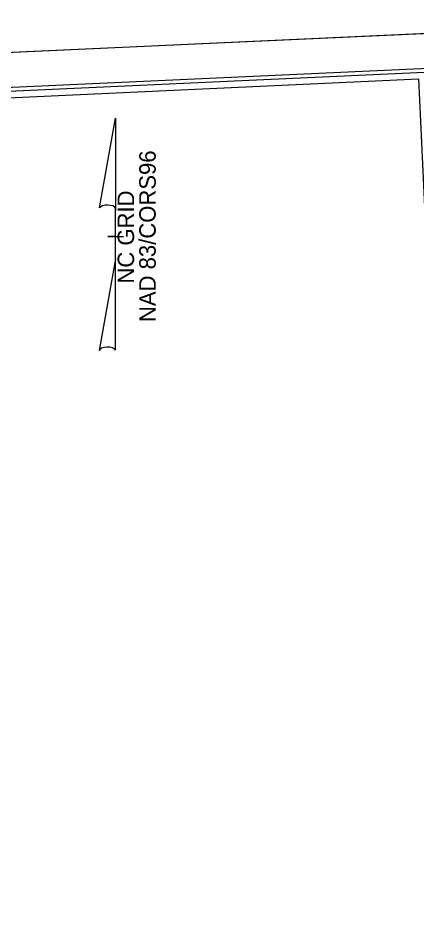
# Model space of a CAD drawing. Extents: x 1191067 to 1191874, y 892813 to 893283.
# Drawn here: x 1191598.1 to 1191700.8, y 893048.3 to 893283.5 of the extents above; entities that cross this region are included whole.
import ezdxf

# ---------------------------------------------------------------- set-up
doc = ezdxf.new("R2010")
doc.units = 0
for name, color, linetype in [('Prop North Arrow NAD83 for Plan Sheets CELL', 7, 'Continuous'), ('Sheet Border Standard 30in CELL', 7, 'Continuous'), ('Sheet Clip Boundary CELL', 7, 'Continuous'), ('Sheet Cutting Line CELL', 7, 'Continuous'), ('Sheet Plot Border Inside CELL', 7, 'Continuous'), ('Sheet Plot Border Outside CELL', 7, 'Continuous')]:
    doc.layers.add(name, color=color, linetype=linetype)

msp = doc.modelspace()

# ---------------------------------------------------------------- linework, layer by layer
at = {"layer": 'Prop North Arrow NAD83 for Plan Sheets CELL'}
for p, q in [((1191619.06, 893234.59), (1191623.16, 893257.76)), ((1191623.19, 893257.76), (1191623.19, 893233.86)), ((1191623.19, 893221.46), (1191623.19, 893234.56)), ((1191623.19, 893233.86), (1191623.19, 893234.54)), ((1191622.96, 893227.26), (1191621.19, 893227.26)), ((1191621.21, 893227.26), (1191625.21, 893227.26)), ((1191623.19, 893221.46), (1191619.01, 893197.84)), ((1191623.21, 893197.94), (1191623.19, 893221.46))]:
    msp.add_line(p, q, dxfattribs=at)
for centre, start_param, end_param in [((1191621.13, 893234.34), 0.216388, 2.908219), ((1191621.13, 893197.75), 0.201328, 3.141593)]:
    msp.add_ellipse(centre, major_axis=(2.11, -0.02), ratio=0.461098, start_param=start_param, end_param=end_param, dxfattribs=at)
at = {"layer": 'Sheet Border Standard 30in CELL'}
msp.add_lwpolyline([(1191783.48, 893273.17), (1191184.11, 893245.75), (1191203.31, 892826.19), (1191802.68, 892853.61)], close=True, dxfattribs=at)
at = {"layer": 'Sheet Clip Boundary CELL'}
msp.add_lwpolyline([(1191202.89, 892905.77), (1191187.26, 893244.08), (1191701.27, 893267.82), (1191704.06, 893207.36), (1191782.86, 893211), (1191795.71, 892932.92), (1191477.62, 892917.95)], close=True, dxfattribs=at)
at = {"layer": 'Sheet Cutting Line CELL'}
msp.add_line((1191789.82, 893283.47), (1191116.92, 893252.68), dxfattribs=at)
at = {"layer": 'Sheet Plot Border Inside CELL'}
msp.add_lwpolyline([(1191788.43, 893274.42), (1191122.53, 893243.95), (1191141.82, 892822.35), (1191807.72, 892852.82)], close=True, dxfattribs=at)
at = {"layer": 'Sheet Plot Border Outside CELL'}
msp.add_lwpolyline([(1191789.82, 893283.47), (1191116.92, 893252.68), (1191137.03, 892813.14), (1191809.93, 892843.93)], close=True, dxfattribs=at)

# ---------------------------------------------------------------- texts
at = {"layer": 'Prop North Arrow NAD83 for Plan Sheets CELL'}
for s, p in [('NAD 83/CORS96', (1191633.55, 893205.18)), ('NC GRID', (1191627.98, 893215.08))]:
    msp.add_text(s, height=4.25, rotation=90, dxfattribs=at).set_placement(p)

doc.saveas('drawing.dxf')
